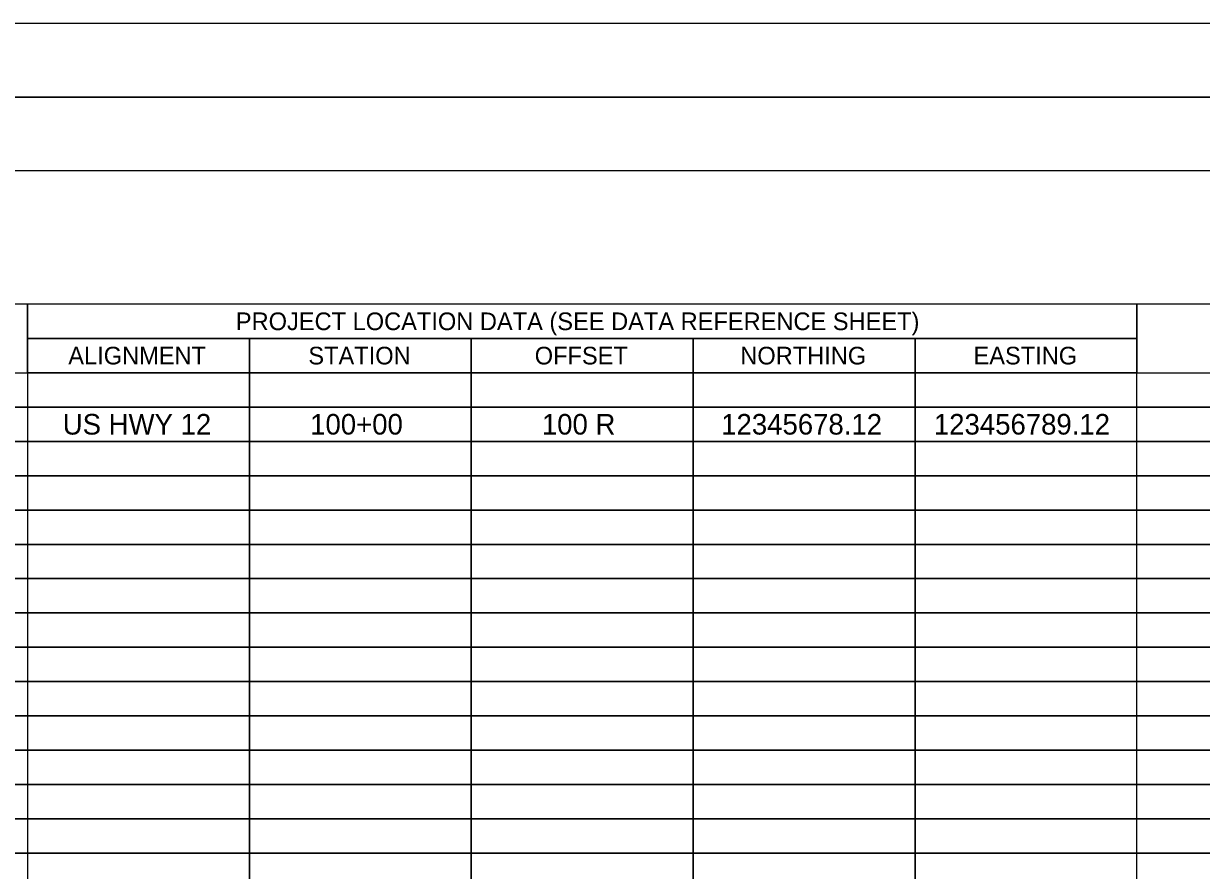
# Model space of a CAD drawing. Extents: x 14330 to 16126, y 15844 to 16994.
# Drawn here: x 15298.3 to 15698.5, y 16706 to 16993.6 of the extents above; entities that cross this region are included whole.
import ezdxf

# ---------------------------------------------------------------- set-up
doc = ezdxf.new("R2010")
doc.units = 0
for name, color, linetype in [('RD_SHT_Bndy', 7, 'Continuous'), ('RD_SHT_Iplotshp', 7, 'Continuous'), ('RD_SHT_TX', 7, 'Continuous')]:
    doc.layers.add(name, color=color, linetype=linetype)

msp = doc.modelspace()

# ---------------------------------------------------------------- linework, layer by layer
at = {"layer": 'RD_SHT_Bndy'}
for p, q in [((16108.25, 16993.63), (14348.25, 16993.63)), ((16108.25, 16968.63), (14348.25, 16968.63)), ((16105.85, 16943.63), (14430.85, 16943.63))]:
    msp.add_line(p, q, dxfattribs=at)
for points in [[(15247.56, 16875.02), (15299.6, 16875.02), (15299.6, 16898.33), (15247.56, 16898.33)], [(15299.6, 16886.67), (15676.58, 16886.67), (15676.58, 16898.33), (15299.6, 16898.33)], [(15676.58, 16875.02), (16080.93, 16875.02), (16080.93, 16898.3), (15676.58, 16898.3)], [(15299.6, 16875.02), (15375, 16875.02), (15375, 16886.67), (15299.6, 16886.67)], [(15375, 16875.02), (15450.39, 16875.02), (15450.39, 16886.67), (15375, 16886.67)], [(15450.39, 16875.02), (15525.79, 16875.02), (15525.79, 16886.67), (15450.39, 16886.67)], [(15525.79, 16875.02), (15601.18, 16875.02), (15601.18, 16886.67), (15525.79, 16886.67)], [(15601.18, 16875.02), (15676.58, 16875.02), (15676.58, 16886.67), (15601.18, 16886.67)], [(15299.6, 16863.36), (15247.56, 16863.36), (15247.56, 16875.02), (15299.6, 16875.02)], [(15299.6, 16863.36), (15375, 16863.36), (15375, 16875.02), (15299.6, 16875.02)], [(15375, 16863.36), (15450.39, 16863.36), (15450.39, 16875.02), (15375, 16875.02)], [(15450.39, 16863.36), (15525.79, 16863.36), (15525.79, 16875.02), (15450.39, 16875.02)], [(15525.79, 16863.36), (15601.18, 16863.36), (15601.18, 16875.02), (15525.79, 16875.02)], [(15601.18, 16863.36), (15676.58, 16863.36), (15676.58, 16875.02), (15601.18, 16875.02)], [(16080.93, 16863.36), (15676.58, 16863.36), (15676.58, 16875.02), (16080.93, 16875.02)], [(15299.6, 16851.71), (15247.56, 16851.71), (15247.56, 16863.36), (15299.6, 16863.36)], [(15299.6, 16851.71), (15375, 16851.71), (15375, 16863.36), (15299.6, 16863.36)], [(15375, 16851.71), (15450.39, 16851.71), (15450.39, 16863.36), (15375, 16863.36)], [(15450.39, 16851.71), (15525.79, 16851.71), (15525.79, 16863.36), (15450.39, 16863.36)], [(15525.79, 16851.71), (15601.18, 16851.71), (15601.18, 16863.36), (15525.79, 16863.36)], [(15601.18, 16851.71), (15676.58, 16851.71), (15676.58, 16863.36), (15601.18, 16863.36)], [(16080.93, 16851.71), (15676.58, 16851.71), (15676.58, 16863.36), (16080.93, 16863.36)], [(15299.6, 16840.05), (15247.56, 16840.05), (15247.56, 16851.71), (15299.6, 16851.71)], [(15299.6, 16840.05), (15375, 16840.05), (15375, 16851.71), (15299.6, 16851.71)], [(15375, 16840.05), (15450.39, 16840.05), (15450.39, 16851.71), (15375, 16851.71)], [(15450.39, 16840.05), (15525.79, 16840.05), (15525.79, 16851.71), (15450.39, 16851.71)], [(15525.79, 16840.05), (15601.18, 16840.05), (15601.18, 16851.71), (15525.79, 16851.71)], [(15601.18, 16840.05), (15676.58, 16840.05), (15676.58, 16851.71), (15601.18, 16851.71)], [(16080.93, 16840.05), (15676.58, 16840.05), (15676.58, 16851.71), (16080.93, 16851.71)], [(15299.6, 16828.4), (15247.56, 16828.4), (15247.56, 16840.05), (15299.6, 16840.05)], [(15299.6, 16828.4), (15375, 16828.4), (15375, 16840.05), (15299.6, 16840.05)], [(15375, 16828.4), (15450.39, 16828.4), (15450.39, 16840.05), (15375, 16840.05)], [(15450.39, 16828.4), (15525.79, 16828.4), (15525.79, 16840.05), (15450.39, 16840.05)], [(15525.79, 16828.4), (15601.18, 16828.4), (15601.18, 16840.05), (15525.79, 16840.05)], [(15601.18, 16828.4), (15676.58, 16828.4), (15676.58, 16840.05), (15601.18, 16840.05)], [(16080.93, 16828.4), (15676.58, 16828.4), (15676.58, 16840.05), (16080.93, 16840.05)], [(15299.6, 16816.74), (15247.56, 16816.74), (15247.56, 16828.4), (15299.6, 16828.4)], [(15299.6, 16816.74), (15375, 16816.74), (15375, 16828.4), (15299.6, 16828.4)], [(15375, 16816.74), (15450.39, 16816.74), (15450.39, 16828.4), (15375, 16828.4)], [(15450.39, 16816.74), (15525.79, 16816.74), (15525.79, 16828.4), (15450.39, 16828.4)], [(15525.79, 16816.74), (15601.18, 16816.74), (15601.18, 16828.4), (15525.79, 16828.4)], [(15601.18, 16816.74), (15676.58, 16816.74), (15676.58, 16828.4), (15601.18, 16828.4)], [(16080.93, 16816.74), (15676.58, 16816.74), (15676.58, 16828.4), (16080.93, 16828.4)], [(15299.6, 16805.09), (15247.56, 16805.09), (15247.56, 16816.74), (15299.6, 16816.74)], [(15299.6, 16805.09), (15375, 16805.09), (15375, 16816.74), (15299.6, 16816.74)], [(15375, 16805.09), (15450.39, 16805.09), (15450.39, 16816.74), (15375, 16816.74)], [(15450.39, 16805.09), (15525.79, 16805.09), (15525.79, 16816.74), (15450.39, 16816.74)], [(15525.79, 16805.09), (15601.18, 16805.09), (15601.18, 16816.74), (15525.79, 16816.74)], [(15601.18, 16805.09), (15676.58, 16805.09), (15676.58, 16816.74), (15601.18, 16816.74)], [(16080.93, 16805.09), (15676.58, 16805.09), (15676.58, 16816.74), (16080.93, 16816.74)], [(15299.6, 16793.43), (15247.56, 16793.43), (15247.56, 16805.09), (15299.6, 16805.09)], [(15299.6, 16793.43), (15375, 16793.43), (15375, 16805.09), (15299.6, 16805.09)], [(15375, 16793.43), (15450.39, 16793.43), (15450.39, 16805.09), (15375, 16805.09)], [(15450.39, 16793.43), (15525.79, 16793.43), (15525.79, 16805.09), (15450.39, 16805.09)], [(15525.79, 16793.43), (15601.18, 16793.43), (15601.18, 16805.09), (15525.79, 16805.09)], [(15601.18, 16793.43), (15676.58, 16793.43), (15676.58, 16805.09), (15601.18, 16805.09)], [(16080.93, 16793.43), (15676.58, 16793.43), (15676.58, 16805.09), (16080.93, 16805.09)], [(15299.6, 16781.78), (15247.56, 16781.78), (15247.56, 16793.43), (15299.6, 16793.43)], [(15299.6, 16781.78), (15375, 16781.78), (15375, 16793.43), (15299.6, 16793.43)], [(15375, 16781.78), (15450.39, 16781.78), (15450.39, 16793.43), (15375, 16793.43)], [(15450.39, 16781.78), (15525.79, 16781.78), (15525.79, 16793.43), (15450.39, 16793.43)], [(15525.79, 16781.78), (15601.18, 16781.78), (15601.18, 16793.43), (15525.79, 16793.43)], [(15601.18, 16781.78), (15676.58, 16781.78), (15676.58, 16793.43), (15601.18, 16793.43)], [(16080.93, 16781.78), (15676.58, 16781.78), (15676.58, 16793.43), (16080.93, 16793.43)], [(15299.6, 16770.12), (15247.56, 16770.12), (15247.56, 16781.78), (15299.6, 16781.78)], [(15299.6, 16770.12), (15375, 16770.12), (15375, 16781.78), (15299.6, 16781.78)], [(15375, 16770.12), (15450.39, 16770.12), (15450.39, 16781.78), (15375, 16781.78)], [(15450.39, 16770.12), (15525.79, 16770.12), (15525.79, 16781.78), (15450.39, 16781.78)], [(15525.79, 16770.12), (15601.18, 16770.12), (15601.18, 16781.78), (15525.79, 16781.78)], [(15601.18, 16770.12), (15676.58, 16770.12), (15676.58, 16781.78), (15601.18, 16781.78)], [(16080.93, 16770.12), (15676.58, 16770.12), (15676.58, 16781.78), (16080.93, 16781.78)], [(15299.6, 16758.47), (15247.56, 16758.47), (15247.56, 16770.12), (15299.6, 16770.12)], [(15299.6, 16758.47), (15375, 16758.47), (15375, 16770.12), (15299.6, 16770.12)], [(15375, 16758.47), (15450.39, 16758.47), (15450.39, 16770.12), (15375, 16770.12)], [(15450.39, 16758.47), (15525.79, 16758.47), (15525.79, 16770.12), (15450.39, 16770.12)], [(15525.79, 16758.47), (15601.18, 16758.47), (15601.18, 16770.12), (15525.79, 16770.12)], [(15601.18, 16758.47), (15676.58, 16758.47), (15676.58, 16770.12), (15601.18, 16770.12)], [(16080.93, 16758.47), (15676.58, 16758.47), (15676.58, 16770.12), (16080.93, 16770.12)], [(15299.6, 16746.81), (15247.56, 16746.81), (15247.56, 16758.47), (15299.6, 16758.47)], [(15299.6, 16746.81), (15375, 16746.81), (15375, 16758.47), (15299.6, 16758.47)], [(15375, 16746.81), (15450.39, 16746.81), (15450.39, 16758.47), (15375, 16758.47)], [(15450.39, 16746.81), (15525.79, 16746.81), (15525.79, 16758.47), (15450.39, 16758.47)], [(15525.79, 16746.81), (15601.18, 16746.81), (15601.18, 16758.47), (15525.79, 16758.47)], [(15601.18, 16746.81), (15676.58, 16746.81), (15676.58, 16758.47), (15601.18, 16758.47)], [(16080.93, 16746.81), (15676.58, 16746.81), (15676.58, 16758.47), (16080.93, 16758.47)], [(15299.6, 16735.16), (15247.56, 16735.16), (15247.56, 16746.81), (15299.6, 16746.81)], [(15299.6, 16735.16), (15375, 16735.16), (15375, 16746.81), (15299.6, 16746.81)], [(15375, 16735.16), (15450.39, 16735.16), (15450.39, 16746.81), (15375, 16746.81)], [(15450.39, 16735.16), (15525.79, 16735.16), (15525.79, 16746.81), (15450.39, 16746.81)], [(15525.79, 16735.16), (15601.18, 16735.16), (15601.18, 16746.81), (15525.79, 16746.81)], [(15601.18, 16735.16), (15676.58, 16735.16), (15676.58, 16746.81), (15601.18, 16746.81)], [(16080.93, 16735.16), (15676.58, 16735.16), (15676.58, 16746.81), (16080.93, 16746.81)], [(15299.6, 16723.5), (15247.56, 16723.5), (15247.56, 16735.16), (15299.6, 16735.16)], [(15299.6, 16723.5), (15375, 16723.5), (15375, 16735.16), (15299.6, 16735.16)], [(15375, 16723.5), (15450.39, 16723.5), (15450.39, 16735.16), (15375, 16735.16)], [(15450.39, 16723.5), (15525.79, 16723.5), (15525.79, 16735.16), (15450.39, 16735.16)], [(15525.79, 16723.5), (15601.18, 16723.5), (15601.18, 16735.16), (15525.79, 16735.16)], [(15601.18, 16723.5), (15676.58, 16723.5), (15676.58, 16735.16), (15601.18, 16735.16)], [(16080.93, 16723.5), (15676.58, 16723.5), (15676.58, 16735.16), (16080.93, 16735.16)], [(15299.6, 16711.84), (15247.56, 16711.84), (15247.56, 16723.5), (15299.6, 16723.5)], [(15299.6, 16711.84), (15375, 16711.84), (15375, 16723.5), (15299.6, 16723.5)], [(15375, 16711.84), (15450.39, 16711.84), (15450.39, 16723.5), (15375, 16723.5)], [(15450.39, 16711.84), (15525.79, 16711.84), (15525.79, 16723.5), (15450.39, 16723.5)], [(15525.79, 16711.84), (15601.18, 16711.84), (15601.18, 16723.5), (15525.79, 16723.5)], [(15601.18, 16711.84), (15676.58, 16711.84), (15676.58, 16723.5), (15601.18, 16723.5)], [(16080.93, 16711.84), (15676.58, 16711.84), (15676.58, 16723.5), (16080.93, 16723.5)], [(15299.6, 16700.19), (15247.56, 16700.19), (15247.56, 16711.84), (15299.6, 16711.84)], [(15299.6, 16700.19), (15375, 16700.19), (15375, 16711.84), (15299.6, 16711.84)], [(15375, 16700.19), (15450.39, 16700.19), (15450.39, 16711.84), (15375, 16711.84)], [(15450.39, 16700.19), (15525.79, 16700.19), (15525.79, 16711.84), (15450.39, 16711.84)], [(15525.79, 16700.19), (15601.18, 16700.19), (15601.18, 16711.84), (15525.79, 16711.84)], [(15601.18, 16700.19), (15676.58, 16700.19), (15676.58, 16711.84), (15601.18, 16711.84)], [(16080.93, 16700.19), (15676.58, 16700.19), (15676.58, 16711.84), (16080.93, 16711.84)]]:
    msp.add_lwpolyline(points, close=True, dxfattribs=at)
at = {"layer": 'RD_SHT_Iplotshp'}
msp.add_lwpolyline([(14329.65, 16968.63), (16125.65, 16968.63), (16125.65, 15868.63), (14329.65, 15868.63)], close=True, dxfattribs=at)

# ---------------------------------------------------------------- texts
at = {"layer": 'RD_SHT_TX'}
for s, height, p in [('PROJECT LOCATION DATA (SEE DATA REFERENCE SHEET)', 6, (15370.41, 16889.5)), ('ALIGNMENT', 6, (15313.47, 16877.85)), ('STATION', 6, (15395.04, 16877.85)), ('OFFSET', 6, (15471.96, 16877.85)), ('NORTHING', 6, (15541.81, 16877.85)), ('EASTING', 6, (15621.05, 16877.85)), ('US HWY 12', 7, (15311.59, 16854.03)), ('100+00', 7, (15395.66, 16854.03)), ('100 R', 7, (15474.39, 16854.03)), ('12345678.12', 7, (15535.32, 16854.03)), ('123456789.12', 7, (15607.58, 16854.03))]:
    msp.add_text(s, height=height, dxfattribs=at).set_placement(p)

doc.saveas('drawing.dxf')
